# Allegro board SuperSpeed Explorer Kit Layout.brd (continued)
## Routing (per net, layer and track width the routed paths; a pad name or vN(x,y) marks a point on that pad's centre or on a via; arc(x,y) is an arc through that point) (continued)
N16679880: length 8.4
  TOP w0.183: v1(36.96,32.75) 36.75,32.54 36.75,32.54 U2.J8 ; R38.1 v2(42.93,31.13)
  L06_SIG2 w0.127: v2(42.93,31.13) 42.09,31.13 40.07,33.15 37.36,33.15 v1(36.96,32.75)
N16679932: length 8.3
  TOP w0.183: R40.1 43.18,28.33 42.9,28.61 v2(42.9,28.89) ; v1(37.76,31.95) 37.55,31.74 37.55,31.74 U2.K7
  L03_SIG1 w0.127: v2(42.9,28.89) 42.19,28.89 39.53,31.56 38.71,31.56 38.32,31.95 v1(37.76,31.95)
N16679936: length 12.1
  TOP w0.183: R53.1 v2(46.61,28.33) ; U2.K8 37.52,32.5 37.52,32.51 v1(37.76,32.75)
  L06_SIG2 w0.127: v1(37.76,32.75) 37.77,32.76 39.9,32.76 42.17,30.49 43.43,30.49 44.96,28.97 45.97,28.97 v2(46.61,28.33)
N16679940: length 14
  TOP w0.183: v1(36.96,31.15) 36.77,30.96 U2.J6 ; R55.1 v2(46.61,25.54)
  L06_SIG2 w0.127: v2(46.61,25.54) 46.08,26.07 43.1,26.07 41.96,27.22 41.96,28.3 39.72,30.54 37.57,30.54 v1(36.96,31.15)
N16679976: length 13.4
  TOP w0.183: U2.J7 36.76,31.74 v1(36.96,31.95) ; R54.1 v2(46.63,26.94)
  L06_SIG2 w0.127: v2(46.63,26.94) 46.63,27.42 46.36,27.7 43.32,27.7 39.48,31.54 37.37,31.54 v1(36.96,31.95)
N16680012: length 13.1
  TOP w0.183: U2.G7 35.16,31.74 v1(35.36,31.95) ; R33.1 v2(42.93,38.11)
  L03_SIG1 w0.127: v1(35.36,31.95) 35.77,32.35 35.77,34.54 35.98,34.76 36.33,34.76 36.56,34.99 36.56,35.39 36.56,35.4 36.56,35.42 39.26,38.11 v2(42.93,38.11)
N16680016: length 9.5
  TOP w0.183: R39.1 v2(42.93,29.73) ; v1(36.16,31.95) 35.94,31.73 35.94,31.73 U2.H7
  L03_SIG1 w0.127: v2(42.93,29.73) 40.7,31.96 39.44,31.96 39.05,32.36 36.57,32.36 v1(36.16,31.95)
N16680036: length 8.6
  TOP w0.183: v2(42.67,27.45) 43.18,26.94 R41.1 ; v1(37.76,31.15) U2.K6
  L03_SIG1 w0.127: v2(42.67,27.45) 42.01,28.11 42.01,28.47 39.33,31.15 v1(37.76,31.15)
N16680040: length 17.1
  TOP w0.183: U2.G6 35.15,30.56 v1(35.36,30.35) ; R57.1 v2(46.61,22.75)
  L06_SIG2 w0.127: v2(46.61,22.75) 45.85,23.51 42.32,23.51 40.44,25.39 40.44,27.55 38.83,29.15 37.15,29.15 36.83,29.48 36.35,29.95 35.76,29.95 v1(35.36,30.35)
N16683802: length 12.4
  TOP w0.183: v1(36.96,28.75) U2.J4 ; R31.1 v2(42.8,20.84)
  L03_SIG1 w0.127: v1(36.96,28.75) 36.96,28.51 37.37,28.1 37.37,27.79 37.61,27.54 38.73,27.54 39.55,26.72 39.55,24.76 42.8,21.51 v2(42.8,20.84)
N16683812: length 13.7
  TOP w0.183: U2.K2 v1(37.76,27.15) ; R29.1 v2(41.4,17.16)
  L03_SIG1 w0.127: v2(41.4,17.16) 41.97,17.73 41.97,18.26 42.04,18.33 42.04,21.16 39.04,24.16 39.04,26.43 38.71,26.75 38.4,26.75 38.01,27.15 v1(37.76,27.15)
N16683838: length 11.9
  TOP w0.183: v1(37.76,26.35) 37.55,26.56 37.55,26.56 U2.K1 ; R26.1 v2(40.01,17.16)
  L06_SIG2 w0.127: v1(37.76,26.35) 38,26.11 38,25.21 40.62,22.58 40.62,17.78 v2(40.01,17.16)
N16683870: length 9
  TOP w0.183: R25.1 v2(40.01,20.84) ; U2.J2 36.75,27.36 36.75,27.36 v1(36.96,27.15)
  L03_SIG1 w0.127: v1(36.96,27.15) 36.96,26.93 37.37,26.53 37.37,24.24 40.01,21.6 v2(40.01,20.84)
N16683912: length 10.6
  TOP w0.183: R28.1 v2(41.4,20.84) ; U2.J3 v1(36.96,27.95)
  L03_SIG1 w0.127: v2(41.4,20.84) 38.16,24.09 38.16,26.51 37.93,26.74 37.6,26.74 37.36,26.99 37.36,27.31 36.96,27.71 v1(36.96,27.95)
N16683932: length 12.5
  TOP w0.183: U2.H2 35.94,27.73 v1(36.16,27.95) ; R20.1 v2(37.21,17.16)
  L06_SIG2 w0.127: v1(36.16,27.95) 36.16,26.32 36.63,25.85 36.63,17.74 v2(37.21,17.16)
N16683942: length 11.9
  TOP w0.183: v1(36.96,26.35) 36.75,26.56 36.75,26.56 U2.J1 ; R24.1 v2(38.61,17.16)
  L06_SIG2 w0.127: v2(38.61,17.16) 39.43,17.98 39.43,23.19 37.22,25.4 37.22,26.09 v1(36.96,26.35)
N16683968: length 10.9
  TOP w0.183: U2.H3 35.94,28.52 v1(36.16,28.75) ; v2(38.73,20.84) 38.61,20.71 R23.1
  L03_SIG1 w0.127: v2(38.73,20.84) 37.97,20.84 36.57,22.25 36.57,28.34 v1(36.16,28.75)
N16684000: length 14.6
  TOP w0.183: v1(34.56,28.75) 34.37,28.94 34.37,28.94 U2.F4 ; R13.1 v2(31.62,17.16)
  L03_SIG1 w0.127: v1(34.56,28.75) 33.78,28.75 33.36,28.33 33.36,27.79 33.36,27.79 33.36,26.19 33.06,25.89 33.06,23.37 32.26,22.57 32.26,22.57 32.26,17.79 v2(31.62,17.16)
N16684042: length 12.5
  TOP w0.183: R18.1 v2(35.81,17.16) ; U2.G2 v1(35.36,27.15)
  L06_SIG2 w0.127: v1(35.36,27.15) 35.76,26.75 35.76,25.98 35.42,25.63 35.42,21.88 34.94,21.4 34.94,17.42 35.2,17.16 v2(35.81,17.16)
N16684068: length 9.1
  TOP w0.183: U2.G3 35.14,28.17 v1(35.36,27.95) ; R17.1 v2(35.81,20.84)
  L03_SIG1 w0.127: v2(35.81,20.84) 34.96,21.7 34.96,27.54 v1(35.36,27.95)
N16684104: length 9.2
  TOP w0.183: U2.F3 34.37,28.14 v1(34.56,27.95) ; R15.1 v2(34.42,20.84)
  L06_SIG2 w0.127: v2(34.42,20.84) 34.42,22.29 34.8,22.67 34.8,25.39 34.11,26.07 34.11,27.5 v1(34.56,27.95)
N16684224: length 17.9
  TOP w0.183: v1(34.56,29.55) 34.36,29.75 34.36,29.75 U2.F5 ; R8.1 v2(27.43,17.16)
  L03_SIG1 w0.127: v1(34.56,29.55) 34.16,29.14 32.8,29.14 32.57,28.91 32.57,28.11 32,27.54 31.2,27.54 30.96,27.3 30.96,24.37 28.19,21.6 28.19,17.92 v2(27.43,17.16)
N16684244: length 20.8
  TOP w0.183: U2.E5 33.2,29.78 33.2,29.78 v1(32.96,29.55) ; R3.1 v2(23.91,19.97)
  L06_SIG2 w0.127: v2(23.91,19.97) 24.23,19.65 32.72,19.65 33.66,20.59 33.66,27.29 33.36,27.59 33.36,29.15 v1(32.96,29.55)
N16684254: length 7
  TOP w0.183: U2.E1 v1(32.96,26.35) ; R14.1 v2(33.02,20.84)
  L06_SIG2 w0.127: v1(32.96,26.35) 32.96,20.9 v2(33.02,20.84)
N16684280: length 15.3
  TOP w0.183: v1(32.96,28.75) 33.17,28.95 33.17,28.95 U2.E4 ; R7.1 v2(27.43,20.84)
  L06_SIG2 w0.127: v2(27.43,20.84) 28.17,20.11 31.98,20.11 32.33,20.46 32.33,20.97 32.56,21.2 32.56,28.35 v1(32.96,28.75)
N16684392: length 12.7
  TOP w0.183: U2.D2 v1(32.16,27.15) ; R10.1 v2(28.83,17.16)
  L03_SIG1 w0.127: v1(32.16,27.15) 31.76,26.74 31.76,23.52 29.44,21.21 29.44,17.77 v2(28.83,17.16)
N16684396: length 7.2
  TOP w0.183: U2.D1 v1(32.16,26.35) ; R12.1 v2(31.62,20.84)
  L06_SIG2 w0.127: v1(32.16,26.35) 32.16,21.38 v2(31.62,20.84)
N16684460: length 13.2
  TOP w0.183: U2.D3 v1(32.96,27.95) ; R11.1 v2(30.23,17.16)
  L03_SIG1 w0.127: v1(32.96,27.95) 32.56,27.54 32.56,23.74 30.86,22.05 30.86,17.79 v2(30.23,17.16)
N16684510: length 16
  TOP w0.183: R6.1 v2(26.04,17.16) ; v1(31.36,28.75) 31.6,28.99 31.6,28.99 U2.C4
  L03_SIG1 w0.127: v2(26.04,17.16) 25.48,17.72 25.48,20.28 29.29,24.09 29.29,26.43 29.74,26.89 29.74,27.83 30.26,28.34 30.71,28.34 31.12,28.75 v1(31.36,28.75)
N16684546: length 9
  TOP w0.183: U2.C2 v1(31.36,27.15) ; R9.1 v2(28.83,20.84)
  L06_SIG2 w0.127: v1(31.36,27.15) 30.96,26.74 30.96,22.61 29.51,21.17 29.16,21.17 v2(28.83,20.84)
N16684554: length 12.7
  TOP w0.183: R5.1 26.04,20.64 26.2,20.8 v2(26.75,20.8) ; U2.D4 32.36,28.95 v1(32.16,28.75)
  L03_SIG1 w0.127: v1(32.16,28.75) 31.76,28.34 31.2,28.34 30.96,28.1 30.96,27.79 30.71,27.54 30.4,27.54 30.17,27.31 30.17,24.34 26.75,20.92 v2(26.75,20.8)
N16684574: length 18.6
  TOP w0.183: v1(32.16,29.55) 32.37,29.76 32.38,29.76 U2.D5 ; R4.1 v2(24.64,17.16)
  L03_SIG1 w0.127: v2(24.64,17.16) 23.98,17.82 23.98,18.88 24.89,19.8 24.89,20.33 27.25,22.7 27.25,26.66 29.74,29.15 31.76,29.15 v1(32.16,29.55)
N16689306: length 3.8
  TOP w0.165: C9.1 26.69,29.85 arc(26.97,30.03) 27.3,30.1 29.84,30.1 arc(30,30.07) 30.13,29.98 U2.A5
N16689332: length 3.8
  TOP w0.165: C8.1 26.69,30.85 arc(26.97,30.66) 27.3,30.6 29.84,30.6 arc(30,30.63) 30.13,30.71 U2.A6
N16689459: length 9.4
  TOP w0.183: U2.C8 v1(31.36,32.75)
  L03_SIG1 w0.127: v2(26.67,36.34) 26.32,35.99 26.32,35.54 28.57,33.29 29.97,33.29 30.51,32.75 v1(31.36,32.75)
  BOTTOM w0.183: R77.1 27.31,36.45 27.19,36.34 v2(26.67,36.34)
N16694632: length 1.8
  TOP w0.183: v2(75.06,33.92) 74.71,34.27 U3.16
  BOTTOM w0.183: v2(75.06,33.92) 75.1,33.88 C38.2
N16695451: length 2.8
  TOP w0.381: v4(79.2,26.85) J8.1 77.38,26.85 76.91,26.38 v4(76.91,26.02)
N16695553: length 5.7
  TOP w0.165: U4.6 73.01,29.94 73.72,30.65 73.72,34.28 arc(73.71,34.46) U3.14
N16695561: length 5.7
  TOP w0.165: U4.4 74.91,29.98 74.21,30.68 74.21,34.28 arc(74.21,34.46) U3.15
N16697030: length 3.8
  TOP w0.183: R59.2 v2(72.71,32.62) U3.12
  BOTTOM w0.183: R63.2 72.54,32.79 v2(72.71,32.62)
N16697037: length 3.3
  TOP w0.183: U3.18 77.31,35.85 C37.1 R61.2
N16734416: length 29.3
  TOP w0.183: R58.2 58.64,25.53 v3(58.64,25.06)
  L03_SIG1 w0.762: v3(62.14,25.06) 61.09,26.11 61.09,40.21 v3(62.14,41.26)
  BOTTOM w0.183: U5.R2 v3(63.41,25.06) ; U5.U2 v3(63.41,22.52) ; U5.T5 v3(58.64,23.79) ; 62.93,40.78 v3(63.41,41.26) ; U5.T6 v3(57.37,23.79) ; U5.U3 v3(62.14,22.52) ; U5.T3 v3(62.14,23.79) ; U5.R3 v3(62.14,25.06) ; 61.66,40.78 v3(62.14,41.26) ; U5.U5 v3(58.64,22.52) ; 59.12,40.78 v3(58.64,41.26) ; U5.U6 v3(57.37,22.52) ; U5.B6 v3(57.37,42.53) ; U5.R6 v3(57.37,25.06) ; U5.R5 v3(58.64,25.06) ; 57.85,40.78 v3(57.37,41.26) ; U5.T2 v3(63.41,23.79)
N16735835: length 24.2
  BOTTOM w0.183: U5.B4 60.96,42.62 60.96,43.39 61.91,44.34 67.32,44.34 68.21,45.23 R66.1 69.14,46.06 71.62,46.06 72.62,47.05 75.01,47.05 78.1,43.96 78.49,43.96 J5.2
N16736019: length 5.6
  BOTTOM w0.183: R67.1 R68.2 61.98,21.73 61.09,22.62 61.09,23.57 U5.T4
N16736247: length 3.6
  BOTTOM w0.183: U5.U4 60.39,21.46 60.34,21.41 R69.2 R70.1
N16824660: length 121.3
  TOP w0.183: v2(67.3,32.92) 67.92,33.55 67.92,33.67 69.6,35.35 U3.8 ; U2.F6 34.32,30.91 34.32,30.91 v1(34.56,31.15)
  L03_SIG1 w0.127: v2(67.3,32.92) 68.71,34.33 68.71,36.21 71.63,39.13 74.3,39.13 76.58,41.42 76.58,43.94 68.18,52.34 16.53,52.34 15.24,51.05 15.24,43.09 18.76,39.57 18.76,36.06 20.89,33.94 25.56,33.94 28.75,30.74 33.4,30.74 33.8,31.15 v1(34.56,31.15)
N16824680: length 117.6
  TOP w0.183: U3.6 67.93,36.35 v2(67.3,35.72) ; v1(32.96,31.95) 33.17,31.74 U2.E7
  L03_SIG1 w0.127: v2(16.38,45.73) 17.53,44.59 17.53,42.3 19.81,40.02 19.81,39.26 22.99,36.08 24.89,36.08 28.07,32.91 29.57,32.91 30.12,32.36 32.56,32.36 v1(32.96,31.95) ; v2(75.08,48.17) 75.08,46.11 75.81,45.39 75.83,45.39 v2(76.33,44.9)
  BOTTOM w0.183: v2(76.33,44.9) 76.33,43.83 75.06,42.56 75.06,35.45 74.55,34.94 68.07,34.94 v2(67.3,35.72) ; v2(75.08,48.17) 75.08,49.01 72.26,51.83 16.51,51.83 15.62,50.94 15.62,46.5 v2(16.38,45.73)
N16824700: length 107.3
  TOP w0.183: U2.C10 v1(31.36,34.35) ; v2(67.3,37.11) 69.33,37.11 69.59,36.85 U3.5
  L03_SIG1 w0.127: v2(67.3,37.11) 68.59,37.11 71.48,39.99 74.22,39.99 75.82,41.59 75.82,43.76 68.01,51.58 17.02,51.58 16.01,50.57 16.01,47.16 17.91,45.27 17.91,42.75 20.38,40.27 25.27,40.27 27.56,37.99 27.56,35.7 29.26,34 29.79,34 30.35,34.56 31.15,34.56 v1(31.36,34.35)
N16824720: length 116.2
  TOP w0.183: v2(67.3,34.32) 67.96,34.32 69.49,35.85 U3.7 ; U2.E8 v1(33.76,31.95)
  L03_SIG1 w0.127: v2(67.3,34.32) 67.94,34.97 67.94,35.95 71.5,39.51 74.21,39.51 76.15,41.45 76.15,43.9 68.15,51.91 16.71,51.91 15.68,50.88 15.68,43.11 19.09,39.71 19.09,36.47 19.81,35.75 24.71,35.75 27.94,32.53 29.36,32.53 30.35,31.54 31.53,31.54 33.36,31.54 v1(33.76,31.95)
N16824740: length 111.8
  TOP w0.183: v2(70.46,30.42) 70.46,30.94 70.63,31.11 70.63,33.6 71.21,34.18 U3.9 ; U2.B11 30.72,34.99 30.72,35.26 v1(30.38,35.6)
  L03_SIG1 w0.127: v2(70.46,30.42) 70.46,30.77 69.22,32.02 67.31,32.02 66.8,32.53 66.8,33.13 66.8,33.13 66.8,34.11 66.8,34.11 66.8,34.52 66.8,34.53 66.8,35.51 66.8,35.51 66.8,35.92 66.8,35.92 66.8,36.91 66.8,36.91 66.8,37.32 69.81,40.32 74.04,40.32 75.12,41.4 75.12,43.06 74.82,43.37 74.82,44.24 67.83,51.22 18.77,51.22 18.24,50.69 18.24,45.53 19.25,44.51 25.23,44.51 26.29,43.46 26.29,43.19 30.73,38.75 30.73,35.95 v1(30.38,35.6)
N16838394:
  vias: v2(6.6,18.94) v2(6.6,17.67) v2(6.6,15.13) v2(6.6,13.86) v2(7.62,18.81) v2(7.62,17.67) v2(7.62,16.4) v2(7.62,15.13) v2(7.62,13.98) v2(8.51,16.4) v2(8.76,18.81) v2(8.89,13.98) v2(9.4,16.4) v2(10.22,18.81) v2(10.22,18.05) v2(10.22,17.29) v2(10.23,16.4) v2(10.22,15.51) v2(10.22,14.75) v2(10.22,13.98) v2(11.05,16.4) v2(11.56,13.98) v2(11.63,12.61) v2(11.63,11.34) v2(11.68,18.81) v2(11.94,16.4) v2(12.83,18.81) v2(12.83,17.67) v2(12.83,16.4) v2(12.83,15.13) v2(12.83,13.98) v2(13.16,12.61) v2(13.16,11.34) v2(14.68,12.61) v2(14.68,11.34)
N16841026:
  vias: v2(11.43,45.48) v2(12.22,44.82)
N16887907: length 33.3
  BOTTOM w0.183: J4.2 46.56,18.68 41.27,18.68 40.77,18.17 40.77,17.03 41.91,15.89 41.91,14.51 42.61,13.81 42.61,10.62 41.78,9.79 36.58,9.79 35.94,9.16 35.94,7.76 35.43,7.25 34.42,7.25 33.77,7.9 33.77,8.89 33.91,9.03 33.91,12.71 33.77,12.86 R74.2
N16887965: length 4.2
  BOTTOM w1.143: L2.1 16.53,23 16.53,21.71 17.4,20.84 17.4,20.52 J3.2
N16887968: length 9
  TOP w1.016: J3.1 15.76,21.75
  TOP w1.143: 15.76,21.75 15.76,23.17 15.01,23.91 J1.1
N16904489: length 12.9
  TOP w0.508: v2(30.45,43.45) 30.57,43.33 33.82,43.33 34.19,42.95 R16.2 35.1,42.96 35.1,42.96 36.1,41.97 36.1,39.26 37.02,38.34 R21.1
  BOTTOM w0.508: C69.1 28.83,42.69 29.59,43.45 v2(30.45,43.45)
  vias: v2(20.45,43.19) v2(20.45,42.05) v2(20.45,40.91) v2(20.45,39.64) v2(21.34,42.05) v2(22.23,42.05) v2(23.05,43.57) v2(23.05,42.81) v2(23.05,42.05) v2(23.05,41.29) v2(23.88,42.05) v2(24.38,39.64) v2(24.77,42.05) v2(25.65,43.19) v2(25.65,42.05) v2(25.65,40.91)
N16904549: length 0.7
  BOTTOM w0.183: 15.88,39.89 15.18,39.89
  vias: v2(14.88,42.03) v2(14.88,41.07) v2(15.59,41.64) v2(23.37,36.84) v2(23.49,37.73)
N16904665: length 4.4
  BOTTOM w0.254: R79.1 21.08,36.55 20.58,37.05 19.98,37.05 19.39,37.65 19.39,38.24 v2(18.27,39.36)
N17011056: length 2.8
  TOP w0.183: v2(78.63,18.16) 78.65,18.14 LED2.2
  BOTTOM w0.183: v2(78.63,18.16) 79.39,18.16 79.52,18.03 R62.2
N17082147: length 5.7
  TOP w0.183: U2.B3 v1(30.56,27.95)
  BOTTOM w0.127: 32.38,24.97 32.38,25.29 31.76,25.92 31.76,27.31 31.53,27.54 30.97,27.54 v1(30.56,27.95)
  BOTTOM w0.183: 32.38,24.97 R75.1
N17153947: length 2.7
  TOP w0.183: R60.1 75.31,41.3 74.66,40.65 74.3,40.65 73.71,40.07 U3.27
N169156910:
  vias: v2(4.32,21.73) v2(4.32,20.84)

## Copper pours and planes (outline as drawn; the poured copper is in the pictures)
AVDD on L06_SIG2: 24.51,38.24 26.42,38.24 27.56,37.1 27.56,32.14 27.94,31.76 29.21,31.76 29.59,32.14 29.59,32.78 28.96,33.41 28.96,39.89 28.57,40.27 24.64,40.27 24.26,39.89 24.26,38.49
GND on TOP: 2.54,0.64 1.19,1.19 0.64,2.54 0.64,9.92 1.02,10.3 5.21,10.3 7.24,8.27 7.24,3.95 7.75,3.44 23.11,3.44 23.8,4.13 23.8,16.98 23.24,17.54 19.69,17.54 19.43,17.29 19.43,12.59 19.3,12.46 17.78,12.46 17.65,12.59 17.65,16.78 16.38,18.05 14.86,18.05 14.48,18.43 14.48,20.84 13.72,21.6 8.64,21.6 6.98,19.95 6.48,19.95 6.35,20.08 6.35,21.86 5.97,22.24 2.54,22.24 2.29,21.98 2.29,19.7 2.54,19.44 4.45,19.44 4.57,19.32 4.57,17.92 4.45,17.79 1.91,17.79 1.27,17.16 0.76,17.16 0.64,17.29 0.64,53.1 1.14,54.47 2.34,55.3 8.8,55.3 8.84,55.26 79.89,55.26 81.03,54.63 81.66,53.5 81.66,32.91 81.53,32.78 77.47,32.78 76.96,32.27 76.96,23.89 77.34,23.51 81.41,23.51 81.66,23.25 81.66,2.54 81.1,1.19 79.76,0.64 ; 51 cut-outs
GND on BOTTOM: 2.54,0.64 1.19,1.19 0.64,2.54 0.64,9.77 0.91,10.05 0.91,10.35 0.64,10.63 0.64,50.43 0.63,52.34 0.63,53.1 1.18,54.54 2.54,55.26 79.38,55.26 80.99,54.59 81.66,52.97 81.66,52.85 81.66,52.85 81.66,50.56 81.66,50.5 81.66,35.57 81.41,35.32 79.88,35.32 79.63,35.07 79.63,23.89 80.14,23.38 80.39,23.64 81.41,23.64 81.66,23.38 81.66,2.54 81.1,1.19 79.76,0.64 ; 96 cut-outs
GND on L02_GND1, L07_GND2: 2.54,0.64 1.19,1.19 0.64,2.54 0.64,53.5 1.19,54.84 2.54,55.4 79.76,55.4 81.1,54.84 81.66,53.5 81.66,2.54 81.1,1.19 79.76,0.64
V1P2 on TOP: 18.67,23.64 18.67,20.84 19.84,19.67 21.34,19.67 21.46,19.8 21.46,20.33 22.1,20.97 22.1,22.62 19.81,22.62 19.43,23 19.43,23.64 19.3,23.76 18.8,23.76
V1P2 on TOP: 10.67,41.29 10.67,38.77 10.39,38.49 6.1,38.49 5.84,38.75 5.84,39.26 5.97,39.38 7.87,39.38 8,39.51 8,41.57 7.9,41.67 6.6,41.67 6.5,41.77 6.5,42.56 6.65,42.71 9.25,42.71
V1P2 on BOTTOM: 18.8,20.71 18.8,23.64 18.96,23.8 20.92,23.8 21.16,23.56 21.16,20.64 21.46,20.33 21.46,19.83 21.34,19.7 19.81,19.7 19.69,19.82 19.69,19.82
V1P2 on BOTTOM: 5.97,41.92 5.97,38.75 6.22,38.49 8.89,38.49 9.4,39 9.4,41.92 9.14,42.18 6.22,42.18
V1P2 on L05_PWR2: 2.54,0.64 1.19,1.19 0.64,2.54 0.64,53.5 1.19,54.84 2.54,55.4 79.76,55.4 81.1,54.84 81.66,53.5 81.66,2.54 81.1,1.19 79.76,0.64
V3P3 on TOP: 19.94,17.03 23.11,17.03 23.29,16.85 23.29,4.18 23.06,3.95 15.77,3.95 15.32,4.41 15.32,8.9 18.33,11.91 19.52,11.91 19.81,12.21 19.81,16.9
V3P3 on TOP: 65.91,30.66 65.91,24.46 66.1,24.27 67.25,24.27 67.44,24.46 67.44,30.68 67.24,30.87 66.13,30.87
V3P3 on TOP: 70.84,38.7 68.5,38.7 68.22,38.98 68.22,40.1 68.48,40.35 70.38,40.35 70.87,39.87 70.87,39.03 70.92,38.98 70.92,38.77
V3P3 on BOTTOM: 22.63,11.72 22.63,17.06 22.3,17.39 18.21,17.39 17.91,17.08 17.91,11.85 15.11,9.06 15.11,4.08 15.37,3.82 18.64,3.82 18.97,4.15 18.97,8.07
V3P3 on BOTTOM: 68.45,41.92 68.07,41.54 68.07,38.21 68.28,38 69.74,38 69.85,38.11 69.85,38.88 71.2,40.22 71.2,41.75 71.02,41.92
V3P3 on L04_PWR1: 2.54,0.64 1.19,1.19 0.64,2.54 0.64,53.5 1.19,54.84 2.54,55.4 79.76,55.4 81.1,54.84 81.66,53.5 81.66,2.54 81.1,1.19 79.76,0.64
VBUS_IN on BOTTOM: 7.77,27.19 6.95,26.37 5.02,26.37 4.19,27.19 3.43,27.19 3.3,27.06 3.3,25.62 2.97,25.29 2.97,22.44 3.17,22.24 3.68,22.24 3.81,22.37 3.81,24.02 5.46,25.67 6.98,25.67 7.24,25.41 7.24,20.71 8.01,19.94 14.95,19.94 15.39,20.38 15.39,24.52 15.01,24.91 12.95,24.91 10.67,27.19
VBUS_IN on L05_PWR2: 0.64,18.33 0.64,34.77 15.11,34.77 15.11,18.33
U3RX_VDDQ on BOTTOM: 21.74,21.32 21.74,23.43 21.89,23.59 25.48,23.59 25.6,23.46 25.6,23.1 25.37,22.87 25.37,21.32
U3RX_VDDQ on L06_SIG2: 23.98,21.35 23.32,22.01 23.32,23.18 23.72,23.59 26.01,23.59 28.22,25.79 28.22,26.84 28.57,27.19 29.79,27.19 30.15,26.84 30.15,23.74 27.76,21.35
U3TX_VDDQ on TOP: 20.32,23.13 19.94,23.51 19.94,24.65 20.02,24.73 21.79,24.73 22.48,25.41 23.37,25.41 24,24.78 24,23.25 23.88,23.13
U3TX_VDDQ on L06_SIG2: 19.02,23.92 18.54,24.4 18.54,29.35 18.94,29.75 23.6,29.75 23.6,28.82 24.41,28.82 24.41,29.75 30.83,29.75 31.03,29.55 31.03,27.69 30.81,27.47 30.02,27.47 29.79,27.7 28.45,27.7 27.86,27.12 27.86,25.9 25.91,23.94 23.19,23.94 23.16,23.92 ; 1 cut-out
USB3_VBUS on TOP: 7.75,4.2 8,3.95 14.61,3.95 14.73,4.08 14.73,9.03 14.61,9.16 10.92,9.16 10.54,9.54 10.54,11.06 8.76,12.84 6.35,12.84 4.32,14.87 0.89,14.87 0.63,14.62 0.63,11.19 1.02,10.81 5.46,10.81 7.75,8.52
USB3_VBUS on TOP: 16,43.32 15.49,43.83 15.49,47.08 15.01,47.56 11.73,47.56 11.43,47.87 11.43,49.14 10.9,49.67 9.86,49.67 9.7,49.82 9.7,52.24 9.87,52.4 20.33,52.4 20.57,52.16 20.57,46.37 20.32,46.11 19.43,46.11 19.18,45.86 19.18,43.83 18.67,43.32
USB3_VBUS on BOTTOM: 1.04,13.25 5.89,13.25 6.2,12.94 9.93,12.94 10.64,12.23 10.64,9.59 10.19,9.13 7.21,9.13 5.77,10.58 1.09,10.58 0.79,10.89 0.79,12.99
USB3_VBUS on BOTTOM: 11.3,5.93 11.32,5.94 11.67,5.94 12.13,6.4 12.13,8.96 12.27,9.1 14.4,9.1 14.61,8.9 14.61,4 14.38,3.77 7.75,3.77 7.49,4.03 7.49,5.75 7.67,5.93
USB3_VBUS on BOTTOM: 6.4,28.51 6.48,28.59 6.48,30.3 6.15,30.63 6.15,33.47 6.6,33.92 7.68,33.92 7.85,34.09 7.85,37.05 7.65,37.25 0.98,37.25 0.74,37 0.74,30.47 1.08,30.12 2.28,30.12 2.57,29.83 2.57,29 3.05,28.51
USB3_VBUS on BOTTOM: 7.67,52.34 14.73,52.34 15.24,51.83 15.24,45.73 15.75,45.23 17.35,45.23 18.8,46.67 18.8,50.69 19.05,50.94 20.19,50.94 20.57,50.56 20.57,47.38 19.56,46.37 19.56,45.96 17.42,43.83 14.61,43.83 14.48,43.96 14.48,47.08 14.07,47.49 10.44,47.49 10.36,47.56 10.36,49.8 10.29,49.87 9.12,49.87 8.94,49.7 8.94,47.54 8.92,47.51 7.59,47.51 7.37,47.74 7.37,52.03
USB3_VBUS on L03_SIG1: 0.64,10.94 0.64,37.35 1.14,37.86 12.57,37.86 17.78,32.65 22.35,32.65 23.24,31.76 23.24,17.29 22.73,16.78 20.19,16.78 20.19,4.08 19.81,3.7 8.38,3.7 7.49,4.59 7.49,9.01 5.94,10.55 1.02,10.55 ; 2 cut-outs
USB3_VBUS on L06_SIG2: 1.33,46.43 0.84,45.94 0.84,28.84 1.27,28.41 5.54,28.41 6.43,29.3 6.43,32.14 7.9,33.62 7.9,37.35 7.87,37.38 7.87,37.73 13.72,43.57 19.35,43.57 20.32,44.54 20.32,50.74 19.46,51.6 10.95,51.6 10.16,50.81 10.16,48.78 7.81,46.43
V_BUS on BOTTOM: 79.63,23.95 79.43,24.14 76.58,24.14 75.95,24.78 74.3,24.78 74.17,24.65 74.17,21.6 74.3,21.48 79.5,21.48 79.63,21.6
V_BUS on L03_SIG1: 75.18,36.97 75.18,35.32 74.7,34.84 71.5,34.84 71.17,34.51 71.17,22.32 72.01,21.48 79.38,21.48 79.76,21.86 79.76,36.97 79.5,37.22 75.44,37.22
VIO on TOP: 38.1,39.13 38.1,36.97 38.35,36.72 39.5,36.72 39.75,36.97 39.75,39.13 39.62,39.26 38.23,39.26
VIO on L04_PWR1: 33.4,11.32 33.66,11.57 33.66,35.83 34.04,36.21 39.42,36.21 40.39,35.24 40.39,10.3 40.01,9.92 24.64,9.92 23.62,8.9 23.62,7.25 23.37,7 19.69,7 18.67,8.01 18.67,8.9 19.18,9.41 20.32,9.41 22.23,11.32
N02063 on BOTTOM: 9.55,28.02 9.55,32.01 9.74,32.2 11.3,32.2 11.48,32.01 11.48,28.04 11.32,27.88 9.69,27.88
N02063 on L06_SIG2: 8.56,36.84 8.56,22.49 9.17,21.88 11.3,21.88 12.01,22.59 12.01,36.84 11.53,37.33 9.04,37.33
N16673785 on L06_SIG2: 19.28,30.14 18.41,31 18.41,37.99 18.67,38.24 20.7,38.24 21.08,37.86 21.08,37.22 22.23,36.08 25.65,36.08 26.09,35.65 26.09,32.48 27.36,31.21 30.58,31.21 30.91,30.87 30.91,30.32 30.73,30.14 24.41,30.14 24.41,31.92 23.6,31.92 23.6,30.14 ; 1 cut-out
N16695427 on TOP: 77.67,26.38 79.48,26.38 79.68,26.58 79.68,29.07 79.5,29.25 77.5,29.25 77.5,32.14 77.65,32.3 81.41,32.3 81.66,32.04 81.66,24.09 81.56,23.99 77.67,23.99
N16695427 on BOTTOM: 80.26,34.74 81.48,34.74 81.66,34.56 81.66,24.42 81.43,24.19 80.26,24.19 80.14,24.32 80.14,34.61
N16695451 on BOTTOM: 76.45,25.03 76.45,26.07 76.81,26.43 77.98,26.43 78.74,27.19 79.38,27.19 79.5,27.06 79.5,25.03 79.12,24.65 76.84,24.65
N16734416 on L03_SIG1: 56.85,41.03 57.38,40.5 63.73,40.5 64.08,40.86 64.08,41.42 63.79,41.71 58.38,41.71 58.14,41.95 58.14,42.84 58.06,42.91 56.95,42.91 56.85,42.81
N16734416 on L03_SIG1: 57.28,22.24 63.5,22.24 63.75,22.49 63.75,25.03 63.5,25.29 57.28,25.29 57.02,25.03 57.02,22.49
N16838394 on TOP: 5.83,19.56 5.46,19.19 5.46,14.49 6.45,13.5 8.87,13.5 10.9,11.47 11.52,10.85 16.29,10.85 16.64,11.19 16.64,16.78 16.26,17.16 14.22,17.16 13.59,17.79 13.59,20.79 13.21,21.17 8.66,21.17 7.05,19.56
N16838394 on BOTTOM: 7.11,19.44 16.54,19.44 17.4,18.58 17.4,12.05 16.36,11.01 11.46,11.01 11.15,11.32 11.15,12.61 10.29,13.48 6.45,13.48 6.17,13.76 0.86,13.76 0.81,13.81 0.81,16.45 1.09,16.73 3,16.73 3.94,17.67 3.94,19.95 4.06,20.08 5.38,20.08 5.46,20.16 5.46,23.25 6.1,23.89 6.48,23.89 6.73,23.64 6.73,19.83
N16841024 on BOTTOM: 9.78,45.61 9.78,43.07 9.52,42.81 6.73,42.81 6.6,42.94 6.6,45.73 6.73,45.86 9.52,45.86
N16841026 on TOP: 9.25,45.56 9.25,44.49 9.37,44.36 12.37,44.36 12.57,44.57 12.57,45.53 12.42,45.68 9.37,45.68
N16841026 on BOTTOM: 10.03,41.85 10.03,40.37 10.16,40.25 11.13,40.25 11.23,40.35 11.23,41.97 12.6,43.35 12.6,45.89 12.5,45.99 10.41,45.99 10.29,45.86 10.29,42.1
N16904489 on BOTTOM: 23.11,39.13 26.04,39.13 26.29,39.38 26.29,41.42 26.67,41.8 29.72,41.8 29.84,41.92 29.84,43.32 29.59,43.57 26.8,43.57 26.54,43.83 26.54,44.59 26.29,44.84 20.32,44.84 20.07,44.59 20.07,42.74 20.02,42.69 18.29,42.69 18.16,42.56 18.16,41.54 18.29,41.42 20.02,41.42 20.07,41.37 20.07,37.86 20.57,37.35 22.73,37.35 22.73,38.75
N16904549 on TOP: 23.11,36.72 23.62,36.72 23.75,36.84 24.38,36.84 24.38,38.24 23.11,38.24 22.99,38.11 22.99,36.84
N16904549 on BOTTOM: 14.48,39.64 17.14,39.64 17.14,42.43 14.48,42.43
N16904549 on BOTTOM: 22.35,36.08 22.35,36.84 22.99,36.84 23.24,37.1 23.24,37.99 23.37,38.11 25.15,38.11 25.15,36.97 24.89,36.72 23.75,36.72 23.11,36.08
N16904549 on L03_SIG1: 11.85,40.74 15.58,40.74 15.88,41.03 15.88,42.05 13.46,44.46 1.14,44.46 0.89,44.21 0.89,42.56 1.27,42.18 10.41,42.18
N16904549 on L06_SIG2: 24,36.34 22.61,36.34 21.59,37.35 21.59,38.11 20.95,38.75 15.24,38.75 14.35,39.64 14.35,42.3 14.61,42.56 16,42.56 16.51,42.05 16.51,41.03 17.08,40.46 22.42,40.46 23.11,39.76 23.11,38.37 23.37,38.11 23.88,38.11 24.38,37.61 24.38,36.72
N16904665 on L03_SIG1: 11.68,40.27 17.75,40.27 18.4,39.62 18.4,38.84 18.27,38.71 1.18,38.71 0.89,39 0.89,41.54 1.02,41.67 10.29,41.67
N169156910 on TOP: 5.97,21.71 5.97,20.59 5.21,19.83 2.79,19.83 2.54,20.08 2.54,21.86 2.67,21.98 5.7,21.98
N169156910 on BOTTOM: 4.06,20.59 4.83,20.59 4.83,23.38 5.71,24.27 6.48,24.27 6.6,24.4 6.6,24.91 6.48,25.03 5.59,25.03 4.32,23.76 4.32,22.11 3.94,21.73 3.94,20.71

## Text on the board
BOTTOM: 600-60198-01 REV04
Ref Des/Assembly Bottom: STAND-OFF [FEMALE] FOR BOARD ON FOUR CORNERS | 15/05/14 | 09/06/14 | 12/06/14 | UPDATED AS PER 630-60194-01 REV02 SCHEMATICS | FIXED DFA ISSUES, ADDED NET TO J7.4 | IMPLEMENTED SILKSCREEN AND FAB CHANGES | 02 | 03 | 04
Board Geometry/Soldermask Bottom: 600-60198-01 SUPERSPEED EXPLORER KIT REV04 SOLDERMASK BOTTOM
Ref Des/Silkscreen Bottom: 1 | HW | 0 | Short | Open | SW_GPIO45 | Button | Function | 4 | K | http://www.cypress.com/go/SuperSpeedExplorerKit | SRAM | EEPROM | QRCODE | BARCODE
TOP: 600-60198-01 REV04
Ref Des/Assembly Top: TP4 | TP5 | TP6
Board Geometry/Soldermask Top: 600-60198-01 SUPERSPEED EXPLORER KIT REV04 SOLDERMASK TOP
Ref Des/Silkscreen Top: 3 | 1 | 1.8V | 3.3V | A1 | POWER LED | GND | VBUS_JUMPER | VBUS | 6 | G | SW_GPIO45 | USB2.0 | CONN | VIO1-3 | RESET | B1 | V3P3 | V1P2 | VIO | CTL15 | USB3.0 | CONNECTOR | NC | DQ31 | DQ15 | CTL12 | DQ30 | PM_2 | CTL11 | DQ14 | DQ29 | PM_1 | CTL10 | DQ13 | PM_0 | DQ12 | CTL9 | DQ28 | IO45 | CTL8 | DQ11 | DQ27 | DQ10 | CTL7 | DQ26 | DQ9 | CTL6 | Rx/MOSI | DQ8 | CTL5 | DQ25 | DQ24 | Tx/MISO | DQ7 | DQ23 | CTL4 | CTS/SSN | DQ6 | CTL3 | DQ22 | DQ5 | CTL2 | DQ21 | RTS/SCK | DQ4 | CTL1 | DQ20 | DQ3 | CTL0 | DQ19 | I2S_WS | DQ2 | DQ18 | I2S_SD | DQ1 | I2S_MCLK | PCLK | DQ17 | DQ0 | I2S_CLK | DQ16 | SCL | SDA | DEBUGGER | INTEGRATED | LED_CTS | 1.2V | PMODE | USBBOOT | I2CBOOT | SEL | DE-SEL | SRAM | ENABLE | CYUSB3KIT-003 | FX3 | SUPERSPEED EXPLORER KIT
DIMENSION: THIS DOUCUMENT CONTAINS CONFIDENTIAL, | OTHERS EXCEPT AS AUTHIRIZED BY CYPRESS | CYPRESS SEMICONDUCTOR PROPERTY | PROPRIETARY INFORMATION THAT IS | DO NOT DISCLOSE TO OR DUPLICATE FOR | DIMENSIONS ARE IN INCHES | 3 PL DECIMALS +/- .005 | PROJECTIONS | THIRD ANGLE | UNLESS OTHERWISE SPECIFIED | 2 PL DECIMALS +/- .010 | TOLERANCES ON; ANGLES +/- 2 | ISSUED | DRAWN | ENGRG | CHECKED | SIGNATURES | : VANAJA | : SHREESHA | : PRAJITH | 12/06/14 | DATE | SCALE | COMPANY | SIZE | C | : 1/1 | FSCM NO | DWG NO | SHEET | REV | X4 | PERFORM | CYPRESS PROPRIETARY | 04 | 02 | 03 | 01 | IMPLEMENTED SILKSCREEN AND FAB CHANGES | UPDATED AS PER 630-60194-01 REV02 SCHEMATICS | FIXED DFA ISSUES, NET ADDED FOR J7.4 | PROTO RELEASE | DESCRIPTION | 198 CHAMPION COURT | SAN JOSE, CA 95134 | 15/05/14 | 09/06/14 | 11/04/14 | (408) 943-2600 | APPROVED | CYPRESS | D | A | B | 4 | 3 | 2 | REVISIONS | SUPERSPEED EXPLORER KIT | 1 | 1 OF 1
DISPLAY_TOP: 600-60198-01 SUPERSPEED EXPLORER KIT REV04 PASTEMASK BOTTOM
TITLE_TOPPASTE: 600-60198-01 SUPERSPEED EXPLORER KIT REV04 PASTEMASK TOP
TITLE_BOTASSY: 620-60198-01 SUPERSPEED EXPLORER KIT REV04 ASSEMBLY BOTTOM
User.5: 620-60198-01 SUPERSPEED EXPLORER KIT REV04 ASSEMBLY TOP | ASSEMBLY TOP
User.6: 600-60198-01 SUPERSPEED EXPLORER KIT REV04 SILKSCREEN TOP
User.7: 600-60198-01 SUPERSPEED EXPLORER KIT REV04 SILKSCREEN BOTTOM
User.23: FAB | FABRICATION DRAWING | 610-60190-01
User.24: 620-60198-01
User.25: LAYERS | L8 | L4 | L6 | L5 | L7 | L3 | L2 | L1 | BOTTOM | PWR2 | GND1 | SIG1 | GND2 | PWR1 | SIG2 | TOP | TYPE | BOTTOM SIDE SOLDER MASK | TOP SIDE SOLDER MASK | COPPER | COPPER+PLATING | STACK INFORMATION | PREPREG | CORE | TOTAL | +PLATING | THICKNESS(MILS) | 4.30 | 61.10 MILS | 0.50 | 9.50 | 0.65 | 4.00 | 1.30 | 18.0 | 0.50MILS | 1.55MM | MILS | 7.2MILS,50 OHM+/-10% | 5MILS,50 OHM +/-10% | BOARD THICKNESS : 0.062" +/-0.006",MATERIAL 370HR | SINGLE ENDED | IMPEDANCE | 47.76 OHM | 49.91 OHM | OHM | 6.5/13/6.5 MILS, | DIFFERENTIAL | 95-99
User.27: PROPRIETARY INFORMATION THAT IS | DO NOT DISCLOSE TO OR DUPLICATE FOR | CYPRESS SEMICONDUCTOR PROPERTY | OTHERS EXCEPT AS AUTHIRIZED BY CYPRESS | THIS DOUCUMENT CONTAINS CONFIDENTIAL, | REV | SHEET | DWG NO | FSCM NO | : 1/1 | C | SIZE | COMPANY | SCALE | DATE | 12/06/14 | PRAJITH | VANAJA | SHREESHA | : | SIGNATURES | CHECKED | ENGRG | DRAWN | ISSUED | TOLERANCES ON; ANGLES +/- 2 | 2 PL DECIMALS +/- .010 | UNLESS OTHERWISE SPECIFIED | THIRD ANGLE | PROJECTIONS | 3 PL DECIMALS +/- .005 | DIMENSIONS ARE IN INCHES | PERFORM | APPROVED | (408) 943-2600 | 11/04/14 | SAN JOSE, CA 95134 | 198 CHAMPION COURT | DESCRIPTION | PROTO RELEASE | 01 | CYPRESS PROPRIETARY | CYPRESS | B | A | D | 04 | 1 OF 1 | 1 | 620-60198-01 | SUPERSPEED EXPLORER KIT | ASSEMBLY BOTTOM | REVISIONS | 2 | 3 | 4
User.29: 1 | 600-60198-01 SUPERSPEED EXPLORER KIT REV04 PRIMARY SIDE
User.30: 2 | 600-60198-01 SUPERSPEED EXPLORER KIT REV04 L02-GND
User.31: 7 | 600-60198-01 SUPERSPEED EXPLORER KIT REV04 L07-GND2
User.32: 4 | 600-60198-01 SUPERSPEED EXPLORER KIT REV04 L04-PWR1
User.33: 5 | 600-60198-01 SUPERSPEED EXPLORER KIT REV04 L05-PWR2
User.34: 3 | 600-60198-01 SUPERSPEED EXPLORER KIT REV04 L03-SIG1
User.35: 6 | 600-60198-01 SUPERSPEED EXPLORER KIT REV04 L06-SIG2
User.36: 8 | 600-60198-01 SUPERSPEED EXPLORER KIT REV04 SECONDARY SIDE
User.37: 4700.00 | 555.00 | 400.00 | 170.00 | 3X | 785.00 | 1530.00 | R72.50 | 330.00 | 1195.00 | 305.00 | 1170.00 | 500.00 | 840.00 | 530.00 | 1600.00 | 425.00 | 175.00 | 765.00 | 325.00 | 725.00
User.45: DATE CODE & UL MARKING | 610-60012-01 REV07   BOARD OUTLINE | 1. RoHS COMPLIANT CERTIFICATION OR MATERIAL DECLARATION REQUIRED | 2. MATERIAL: | 3. DRILLING: | 4. PLATING: | 5. MARKING: | 6. FINAL FABRICATION: | 9. MANUFACTURE BOARD TO BE IN ACCORDANCE WITH PERFORMANCE STANDARD | 10.MAXIMUM WARP OR TWIST SHALL NOT EXCEED 0.005" PER INCH | 7. FINISH: | 8. BOARDS SHALL BE PURCHASED FROM UL RECOGNIZED VENDORS ONLY AND SHALL BE | C. OVERALL METAL TO METAL THICKNESS AS SPECIFIED IN THE CROSS SECTION | A. IS410 OR EQUIVALENT. MATERIAL MUST CONFORM TO UL94V-0. | B. USE HTE COPPER, AS SPECIFIED IN THE CROSS SECTION DIAGRAM. | B.FABRICATOR TO PLACE DATE CODE AND UL LOGO ON SECONDARY SIDE IN SILKSCREEN | A. DIAMETERS IN DRILL TABLE ARE FINISHED HOLE SIZES +/-.003 TOL. | B. TEARDROP ALLOWED ON ENTRY OF VIA ON EVERY TRACE LAYER. | A. SILKSCREEN IN WHITE NON-CONDUCTIVE EPOXY INK ON PRIMARY SIDE OF THE | B. ALL VIAS THAT ARE PLACED ON EXPOSED PADS MUST BE PLUGGED WITH SOLDERMASK INK ON THE SIDE | A. SOLDERMASK PRIMARY AND SECONDARY SIDE OF BOARD USING LIQUID PHOTOIMAGABLE | A. SHALL BE ELECTROLYTIC NICKEL/GOLD. ELECTROLESS NIKEL / IMMERSION GOLD. (ENIG) | C. GOLD THICKNESS: 3-10 MICROINCHES. | FLAMABILITY RATING (94-V), DATE CODE (WWYY), AND RoHS COMPLIANT SYMBOL. | IPC-6011/6012 CLASS 2 BOARD TO BE INSPECTED PER IPC-600-A CLASS 2. | B. NICKEL THICKNESS. 100-200 MICROINCHES. | MARKED IN SILKSCREEN ON SECONDARY SIDE OF BOARD WITH VENDORS UL IDENT. | WHERE IT IS MASKED IN THE SOLDER MASK FILM.THIS IS TO AVOID SOLDER FLOW THROUGH VIA HOLE. | COPPER PLATING IN THRU-HOLES .001 min. | BOARD OR BOTH SIDES IF APPLICABLE. | UNLESS OTHERWISE SPECIFIED IN DRILL TABLE. | MASK MATERIAL OVER BARE COPPER..PER IPC-SM-840. MASK ARTWORKS PROVIDED | ARE 1:1. SOLDERMASK COLOR **BLUE** | A. FABRICATOR TO ADD TEST STRUCTURES OR CUPONS AS NEEDED | B. T-LINE IMPEDANCE TO BE TESTED OR GURANTEED WITHIN 10% IF SPECIFIED IN | 13.LAYER LADDER PROVIDED IN THE PCB SHOULD NOT BE MASKED | 14.DESIGN TEAM: | 12.MINIMUM TRACE WIDTH : 5 MILS | 11.TESTING: | CAM TEAM: | THE CROSS SECTION.  TOLERANCE TO BE +/-10% UNLESS OTHERWISE SPECIFIED | MINIMUM SPACING : 4.1 MILS | IN SOLDER MASK LAYER, COPPER PAD HAS BEEN ENABLED INSTEAD OF MASK PAD | FOR PROVIDING 1:1 SOLDER MASK OPENING FOR PADS ALL OVER THE BOARD. | PLS DELETE NOTE 14 DURING GERBER GENERATION | NOTES:(UNLESS OTHERWISE SPECIFIED) | FIGURE | SIZE | 8.0 | 10.0 | 12.0 | 30.0 | 39.0 | 40.0 | 40.16 | 43.0 | 95.0 | 118.0 | 50.24x26.62 | DRILL CHART: TOP to BOTTOM | ALL UNITS ARE IN MILS | TOLERANCE | +3.0/-3.0 | +2.0/-2.0 | PLATED | NON-PLATED | QTY | 224 | 310 | 151 | 5 | 4 | 80 | 2 | 8
